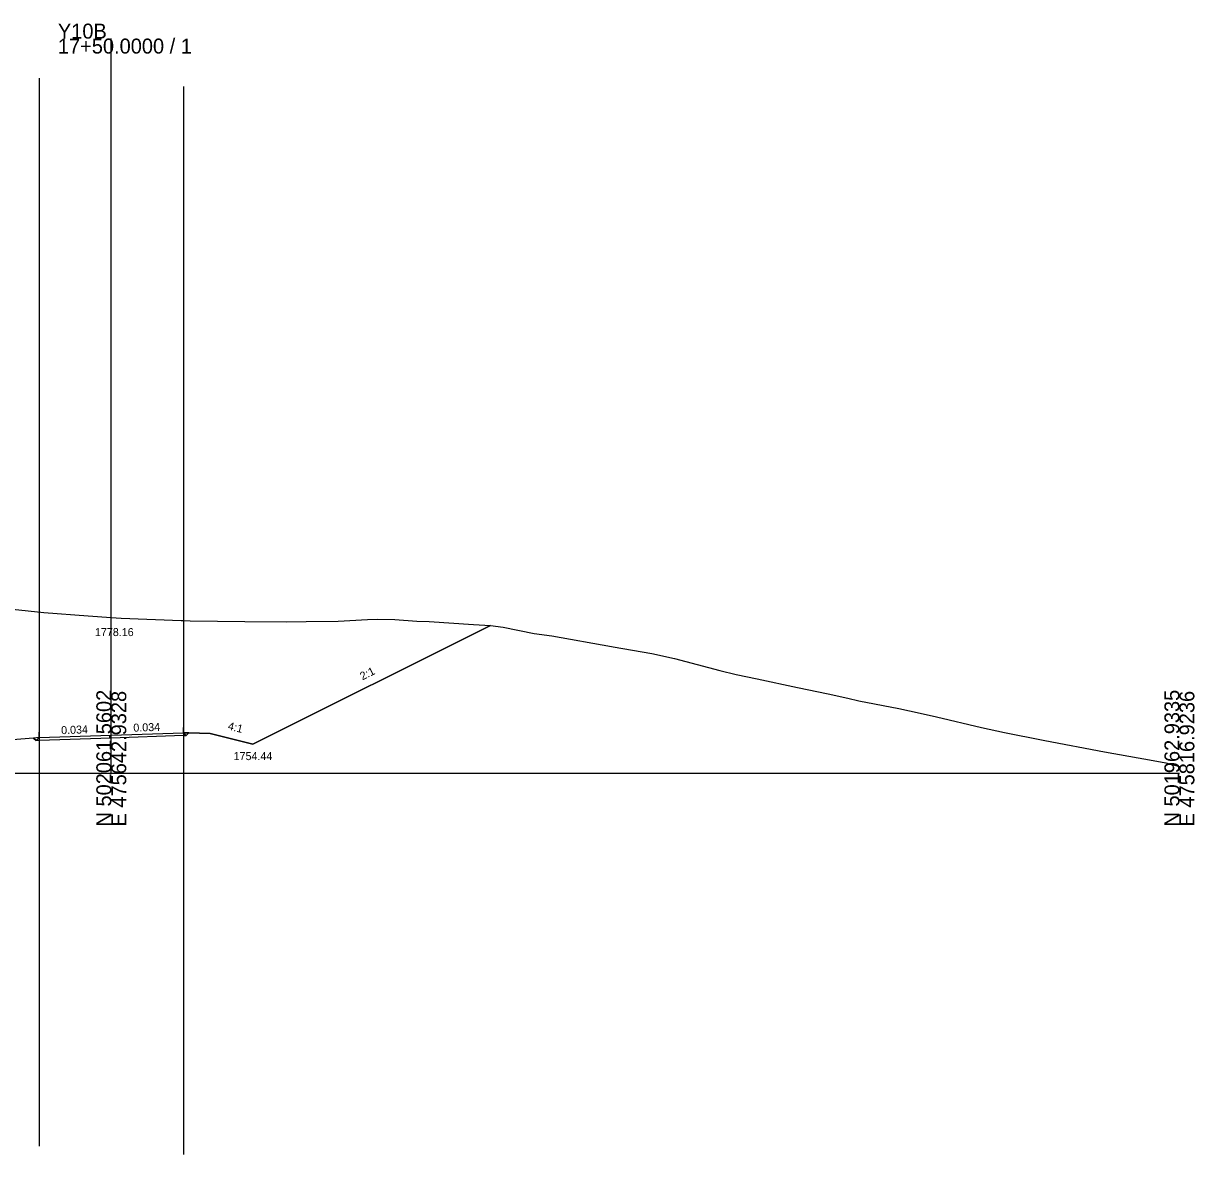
# Model space of a CAD drawing. Extents: x -26 to 1803, y -10 to 9558.
# Drawn here: x 183.5 to 402.8, y 7428.6 to 7640.4 of the extents above; entities that cross this region are included whole.
import ezdxf

# ---------------------------------------------------------------- set-up
doc = ezdxf.new("R2010")
doc.units = 0
for name, color, linetype in [('Exist Cross Section Cell', 7, 'Continuous'), ('Exist XS Center Line Elevation Label', 7, 'Continuous'), ('Exist XS Ground Line', 7, 'Continuous'), ('Prop XS Ditch Slope Text', 7, 'Continuous'), ('Prop XS Ditch Standard Text', 7, 'Continuous'), ('Prop XS Dump Level', 7, 'Continuous'), ('Prop XS Earthwork Shape', 7, 'Continuous'), ('Prop XS EOT Tick Mark', 7, 'Continuous'), ('Prop XS Finish Grade', 7, 'Continuous'), ('Prop XS Finish Grade Earthwork', 7, 'Continuous'), ('Prop XS Finish Grade Pavement', 7, 'Continuous'), ('Prop XS Hydro Typical Ditch Data', 7, 'Continuous'), ('Prop XS Pvmt Edge Slope', 7, 'Continuous'), ('Prop XS SE Text', 7, 'Continuous'), ('Prop XS Shoulder Borrow Shape', 7, 'Continuous'), ('Prop XS Side Slope Text', 7, 'Continuous'), ('Prop XS Subgrade Earthwork', 7, 'Continuous'), ('Scratch_Level_2', 7, 'Continuous')]:
    doc.layers.add(name, color=color, linetype=linetype)

msp = doc.modelspace()

# ---------------------------------------------------------------- linework, layer by layer
at = {"layer": 'Exist Cross Section Cell'}
for p, q in [((200, 7500), (200, 7637.55)), ((0, 7500), (200, 7500)), ((200, 7500), (400, 7500))]:
    msp.add_line(p, q, dxfattribs=at)
at = {"layer": 'Exist XS Ground Line'}
msp.add_lwpolyline([(175.54, 7531.31), (187.37, 7530.05), (195.65, 7529.45), (200, 7529.16), (201.87, 7529.03), (213.11, 7528.59), (213.46, 7528.57), (214.75, 7528.54), (225, 7528.39), (232.83, 7528.31), (236.5, 7528.38), (242.51, 7528.48), (247.99, 7528.76), (249.85, 7528.8), (253.11, 7528.76), (257.18, 7528.48), (259.49, 7528.38), (267.84, 7527.84), (270.99, 7527.66), (273.39, 7527.34), (279.2, 7526.14), (282.49, 7525.71), (293.68, 7523.7), (293.98, 7523.63), (301.21, 7522.43), (305.48, 7521.45), (313.96, 7519.19), (316.98, 7518.48), (320.92, 7517.64), (328.47, 7516.04), (334.24, 7514.83), (337.9, 7514.03), (339.97, 7513.55), (347.47, 7512.07), (351.47, 7511.23), (354.52, 7510.53), (362.96, 7508.56), (367.25, 7507.63), (374.46, 7506.16), (374.81, 7506.1), (385.96, 7504.01), (395.09, 7502.36), (397.46, 7501.92), (400, 7501.23)], dxfattribs=at)
at = {"layer": 'Prop XS Dump Level'}
for p, q in [((186.49, 7506.65), (200, 7507.11)), ((200, 7507.11), (213.52, 7507.57))]:
    msp.add_line(p, q, dxfattribs=at)
at = {"layer": 'Prop XS Earthwork Shape'}
msp.add_lwpolyline([(175.54, 7531.31), (187.37, 7530.05), (195.65, 7529.45), (200, 7529.16), (201.87, 7529.03), (213.11, 7528.59), (213.46, 7528.57), (214.75, 7528.54), (225, 7528.39), (232.83, 7528.31), (236.5, 7528.38), (242.51, 7528.48), (247.99, 7528.76), (249.85, 7528.8), (253.11, 7528.76), (257.18, 7528.48), (259.49, 7528.38), (267.84, 7527.84), (270.98, 7527.66), (226.52, 7505.44), (218.52, 7507.44), (214.54, 7507.54), (214.04, 7507.05), (213.52, 7507.03), (200, 7506.57), (186.49, 7506.11), (185.93, 7506.09), (185.45, 7506.57), (181.49, 7506.25)], dxfattribs=at)
at = {"layer": 'Prop XS EOT Tick Mark'}
for p, q in [((186.49, 7506.65), (186.49, 7507.65)), ((213.52, 7507.57), (213.52, 7508.57))]:
    msp.add_line(p, q, dxfattribs=at)
at = {"layer": 'Prop XS Finish Grade'}
for p, q in [((186.49, 7506.65), (185.45, 7506.57)), ((213.52, 7507.57), (214.54, 7507.54))]:
    msp.add_line(p, q, dxfattribs=at)
at = {"layer": 'Prop XS Finish Grade Earthwork'}
for p, q in [((226.52, 7505.44), (270.98, 7527.66)), ((185.45, 7506.57), (181.49, 7506.25)), ((214.54, 7507.54), (218.52, 7507.44)), ((218.52, 7507.44), (226.52, 7505.44))]:
    msp.add_line(p, q, dxfattribs=at)
at = {"layer": 'Prop XS Finish Grade Pavement'}
for p, q in [((186.49, 7506.65), (200, 7507.11)), ((200, 7507.11), (213.52, 7507.57))]:
    msp.add_line(p, q, dxfattribs=at)
at = {"layer": 'Prop XS Hydro Typical Ditch Data'}
for p, q in [((226.52, 7505.44), (270.98, 7527.66)), ((218.52, 7507.44), (226.52, 7505.44))]:
    msp.add_line(p, q, dxfattribs=at)
at = {"layer": 'Prop XS Pvmt Edge Slope'}
for p, q in [((186.49, 7506.65), (185.93, 7506.09)), ((213.52, 7507.57), (214.04, 7507.05))]:
    msp.add_line(p, q, dxfattribs=at)
at = {"layer": 'Prop XS Shoulder Borrow Shape'}
for points in [[(186.49, 7506.65), (185.45, 7506.57), (185.93, 7506.09)], [(213.52, 7507.57), (214.04, 7507.05), (214.54, 7507.54)]]:
    msp.add_lwpolyline(points, close=True, dxfattribs=at)
at = {"layer": 'Prop XS Subgrade Earthwork'}
for p, q in [((185.93, 7506.09), (185.45, 7506.57)), ((200, 7506.57), (186.49, 7506.11)), ((213.52, 7507.03), (200, 7506.57)), ((213.52, 7507.03), (214.04, 7507.05)), ((214.04, 7507.05), (214.54, 7507.54)), ((186.49, 7506.11), (185.93, 7506.09))]:
    msp.add_line(p, q, dxfattribs=at)
at = {"layer": 'Scratch_Level_2'}
for p, q in [((186.48, 7630.14), (186.48, 7430.14)), ((213.52, 7628.56), (213.52, 7428.56))]:
    msp.add_line(p, q, dxfattribs=at)

# ---------------------------------------------------------------- texts
at = {"layer": 'Exist Cross Section Cell'}
for s, p in [('Y10B', (190, 7637.55)), ('17+50.0000 / 1', (190, 7634.75))]:
    msp.add_text(s, height=2.8, dxfattribs=at).set_placement(p)
for s, p in [('N 502061.5602', (200, 7490)), ('E 475642.9328', (202.8, 7490)), ('N 501962.9335', (400, 7490)), ('E 475816.9236', (402.8, 7490))]:
    msp.add_text(s, height=2.8, rotation=90, dxfattribs=at).set_placement(p)
at = {"layer": 'Exist XS Center Line Elevation Label'}
msp.add_text('1778.16', height=1.5, dxfattribs=at).set_placement((196.94, 7525.66))
at = {"layer": 'Prop XS Ditch Slope Text'}
msp.add_text('4:1', height=1.5, rotation=345.9678, dxfattribs=at).set_placement((221.73, 7508.18))
at = {"layer": 'Prop XS Ditch Standard Text'}
msp.add_text('1754.44', height=1.5, dxfattribs=at).set_placement((222.9, 7502.44))
at = {"layer": 'Prop XS Dump Level'}
msp.add_text('Case1', height=0.04, dxfattribs=at).set_placement((218.52, 7507.4))
at = {"layer": 'Prop XS SE Text'}
for p in [(190.63, 7507.29), (204.15, 7507.75)]:
    msp.add_text('0.034', height=1.5, rotation=1.9481, dxfattribs=at).set_placement(p)
at = {"layer": 'Prop XS Side Slope Text'}
msp.add_text('2:1', height=1.5, rotation=26.5582, dxfattribs=at).set_placement((247.02, 7517.36))

doc.saveas('drawing.dxf')
